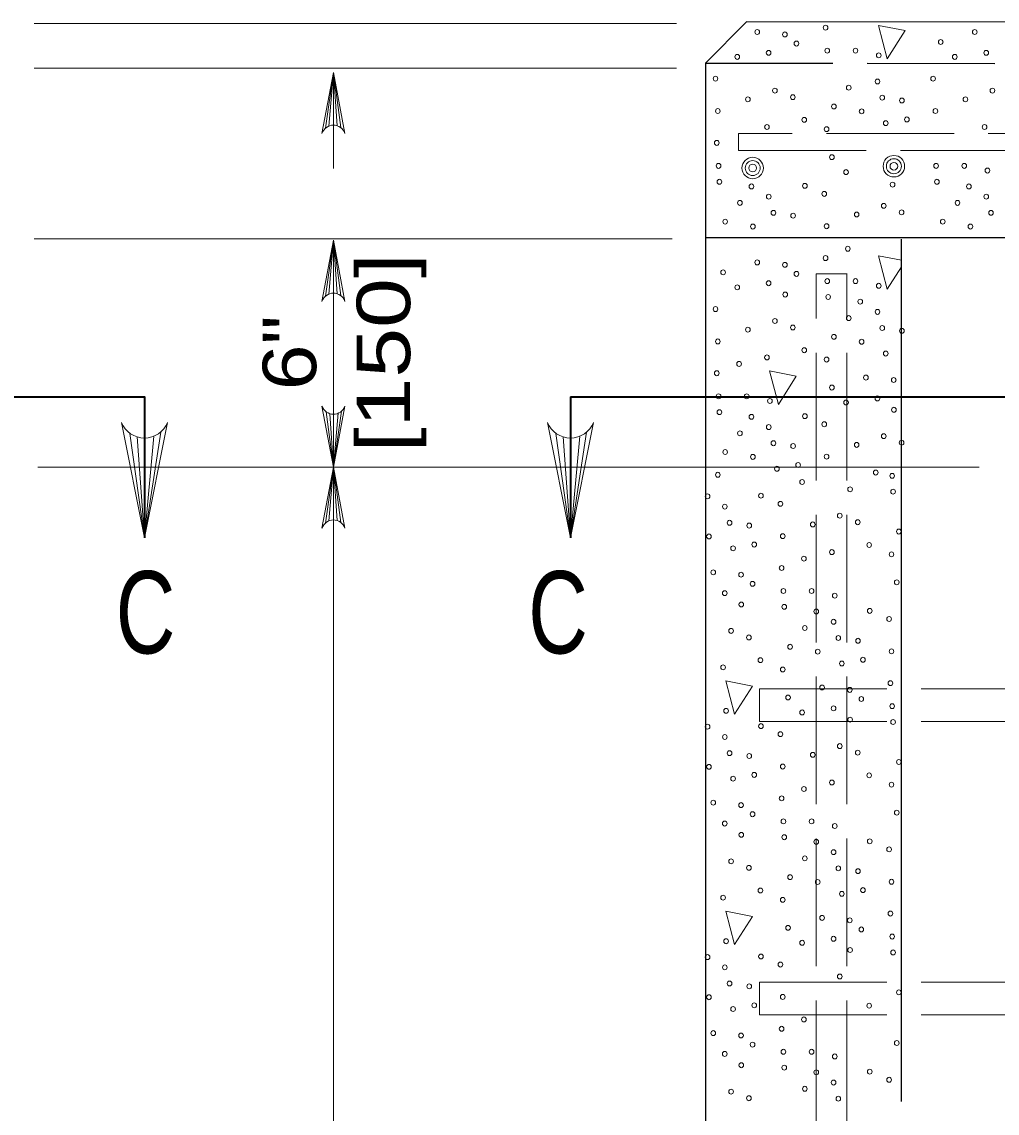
# Model space of a CAD drawing. Extents: x 1329.9 to 1363.9, y 715.5 to 737.5.
# Drawn here: x 1338.52 to 1341.364, y 730.929 to 734.111 of the extents above; entities that cross this region are included whole.
import ezdxf
from ezdxf.enums import TextEntityAlignment as Align

# ---------------------------------------------------------------- set-up
doc = ezdxf.new("R2010")
doc.units = 0
doc.header["$LTSCALE"] = 0.062
doc.linetypes.add('LONG_DASHED', pattern=[7.5, 6, -1.5])
doc.layers.add('1', color=7, linetype='Continuous', lineweight=13)

msp = doc.modelspace()

# ---------------------------------------------------------------- linework, layer by layer
at = {"layer": '1'}
for p, q in [((1338.55558, 734.106), (1340.42958, 734.106)), ((1341.018, 734.10017), (1341.04367, 734.00275)), ((1341.09592, 734.08492), (1341.018, 734.10017)), ((1341.04367, 734.00275), (1341.09592, 734.08492)), ((1338.55558, 733.97533), (1340.42958, 733.97533)), ((1339.40517, 733.80017), (1339.42875, 733.96325)), ((1339.415, 733.80633), (1339.42875, 733.96325)), ((1339.42875, 733.80917), (1339.42875, 733.96325)), ((1339.4395, 733.8075), (1339.42875, 733.96325)), ((1339.45, 733.80208), (1339.42875, 733.96325)), ((1339.42875, 733.68275), (1339.42875, 733.96325)), ((1340.61017, 733.7845), (1340.61017, 733.73575)), ((1340.61017, 733.7845), (1340.69425, 733.7845)), ((1340.61017, 733.73575), (1340.69425, 733.73575)), ((1338.55558, 733.47808), (1340.41692, 733.47808)), ((1339.40517, 733.31058), (1339.42875, 733.47375)), ((1339.415, 733.31675), (1339.42875, 733.47375)), ((1339.42875, 733.31958), (1339.42875, 733.47375)), ((1339.4395, 733.31792), (1339.42875, 733.47375)), ((1339.45, 733.3125), (1339.42875, 733.47375)), ((1341.018, 733.4285), (1341.04367, 733.33117)), ((1341.08508, 733.41542), (1341.018, 733.4285)), ((1341.04367, 733.33117), (1341.08508, 733.39633)), ((1339.40742, 732.9735), (1339.42875, 732.81225)), ((1339.41792, 732.96808), (1339.42875, 732.81225)), ((1339.45225, 732.97542), (1339.42875, 732.81225)), ((1339.44242, 732.96925), (1339.42875, 732.81225)), ((1339.42875, 732.96642), (1339.42875, 732.81225)), ((1338.83542, 732.91075), (1338.878, 732.60617)), ((1338.8565, 732.9005), (1338.878, 732.60617)), ((1338.92508, 732.91433), (1338.878, 732.60617)), ((1338.90542, 732.90267), (1338.878, 732.60617)), ((1338.878, 732.89733), (1338.878, 732.60617)), ((1340.07742, 732.91075), (1340.12008, 732.60617)), ((1340.0985, 732.9005), (1340.12008, 732.60617)), ((1340.16717, 732.91433), (1340.12008, 732.60617)), ((1340.14742, 732.90267), (1340.12008, 732.60617)), ((1340.12008, 732.89733), (1340.12008, 732.60617)), ((1338.567, 732.81183), (1340.16533, 732.81183)), ((1339.40517, 732.64917), (1339.42875, 732.81225)), ((1339.415, 732.65533), (1339.42875, 732.81225)), ((1339.42875, 732.65817), (1339.42875, 732.81225)), ((1339.4395, 732.6565), (1339.42875, 732.81225)), ((1339.45, 732.651), (1339.42875, 732.81225)), ((1340.16533, 732.81183), (1341.31183, 732.81183))]:
    msp.add_line(p, q, dxfattribs=at)
at = {"layer": '1', "lineweight": 25}
for p, q in [((1340.51358, 733.98983), (1340.51358, 732.78242)), ((1340.51358, 733.48175), (1341.09175, 733.48175)), ((1341.08508, 732.804), (1341.08508, 733.47675)), ((1341.09175, 733.48175), (1343.775, 733.48175)), ((1341.08508, 730.96275), (1341.08508, 732.804)), ((1340.51358, 732.78242), (1340.51358, 729.46942))]:
    msp.add_line(p, q, dxfattribs=at)
at = {"layer": '1', "linetype": 'LONG_DASHED', "lineweight": 25}
msp.add_line((1340.51358, 733.98983), (1343.61975, 733.988), dxfattribs=at)
at = {"layer": '1', "linetype": 'LONG_DASHED'}
for p, q in [((1344.5425, 733.7845), (1340.61017, 733.7845)), ((1340.61017, 733.73575), (1344.5425, 733.73575)), ((1340.83683, 733.37567), (1340.92658, 733.37567)), ((1340.67083, 732.1655), (1345.98667, 732.1655)), ((1340.67083, 732.1655), (1340.67083, 732.07058)), ((1340.67083, 732.07058), (1345.98667, 732.07058)), ((1340.67083, 731.31067), (1345.98667, 731.31067)), ((1340.67083, 731.31067), (1340.67083, 731.21567)), ((1340.67083, 731.21567), (1345.98667, 731.21567))]:
    msp.add_line(p, q, dxfattribs=at)
at = {"layer": '1', "lineweight": 35}
msp.add_line((1340.12008, 733.01742), (1340.12008, 732.60617), dxfattribs=at)
at = {"layer": '1', "lineweight": 25}
msp.add_lwpolyline([(1343.61975, 734.10892), (1340.63383, 734.1105), (1340.51358, 733.98983)], dxfattribs=at)
at = {"layer": '1'}
for points in [[(1339.39508, 733.78517), (1339.42875, 733.96325), (1339.46233, 733.78517)], [(1339.39508, 733.29558), (1339.42875, 733.47375), (1339.46233, 733.29558)], [(1339.42875, 732.83242), (1339.42875, 733.08692), (1339.42875, 733.47375)], [(1339.46233, 732.99033), (1339.42875, 732.81225), (1339.39508, 732.99033)], [(1338.94533, 732.94267), (1338.878, 732.60617), (1338.81075, 732.94267)], [(1340.18733, 732.94267), (1340.12008, 732.60617), (1340.05275, 732.94267)], [(1339.39508, 732.63417), (1339.42875, 732.81225), (1339.46233, 732.63417)], [(1339.42875, 725.87033), (1339.42875, 729.46942), (1339.42875, 732.83242)]]:
    msp.add_lwpolyline(points, dxfattribs=at)
at = {"layer": '1', "linetype": 'LONG_DASHED'}
for points in [[(1340.83683, 729.40367), (1340.83683, 729.46942), (1340.83683, 733.37567)], [(1340.92608, 729.41367), (1340.92608, 729.46942), (1340.92608, 733.37567)]]:
    msp.add_lwpolyline(points, dxfattribs=at)
at = {"layer": '1'}
for points in [[(1340.70075, 733.09267), (1340.72642, 732.99533), (1340.77867, 733.0775)], [(1340.57275, 732.18917), (1340.59842, 732.09183), (1340.65067, 732.174)], [(1340.57275, 731.5175), (1340.59842, 731.42017), (1340.65067, 731.50233)]]:
    msp.add_lwpolyline(points, close=True, dxfattribs=at)
at = {"layer": '1', "lineweight": 35}
for points in [[(1332.47342, 733.01742), (1338.878, 733.01742), (1338.878, 732.60617)], [(1340.12008, 733.01742), (1346.51367, 733.01742), (1346.51367, 732.60617)]]:
    msp.add_lwpolyline(points, dxfattribs=at)
at = {"layer": '1'}
for centre, radius in [((1340.65149, 733.68422), 0.03133), ((1340.65149, 733.68422), 0.0219), ((1340.65149, 733.68422), 0.01122), ((1341.06314, 733.68951), 0.03133), ((1341.06314, 733.68951), 0.0219), ((1341.06314, 733.68951), 0.01122)]:
    msp.add_circle(centre, radius, dxfattribs=at)
for centre in [(1338.87794, 732.9698), (1340.11998, 732.9698)]:
    msp.add_arc(centre, 0.07261, 202.08782, 337.91395, dxfattribs=at)
for centre in [(1340.66458, 734.08078), (1340.74541, 734.07378), (1340.86388, 734.09343), (1341.29897, 734.08078), (1340.77908, 734.0472), (1341.19964, 734.05173), (1340.60637, 734.00819), (1340.69799, 734.02), (1340.86901, 734.02632), (1340.95127, 734.02632), (1341.01889, 734.01272), (1341.24077, 734.00819), (1341.33239, 734.02), (1340.54293, 733.94472), (1341.17733, 733.94472), (1340.71628, 733.90996), (1340.9315, 733.91841), (1341.01545, 733.93654), (1341.35068, 733.90996), (1340.63746, 733.8846), (1340.76851, 733.89093), (1341.0292, 733.88942), (1341.08656, 733.88119), (1341.27185, 733.8846), (1340.5498, 733.85035), (1340.88841, 733.86373), (1340.96919, 733.84951), (1341.1842, 733.85035), (1340.80187, 733.82471), (1341.0394, 733.81503), (1341.1011, 733.82595), (1340.69312, 733.80384), (1340.867, 733.79751), (1341.32752, 733.80384), (1340.54668, 733.75761), (1340.55181, 733.6905), (1340.88244, 733.71591), (1341.18621, 733.6905), (1341.26847, 733.6905), (1340.92357, 733.67236), (1341.33609, 733.6769), (1340.55435, 733.64427), (1340.64776, 733.63067), (1340.80361, 733.63246), (1341.05941, 733.63595), (1341.18875, 733.64427), (1341.28216, 733.63067), (1340.69825, 733.60072), (1340.86013, 733.60889), (1341.33265, 733.60072), (1340.6143, 733.58259), (1341.03348, 733.57414), (1341.2487, 733.58259), (1340.57121, 733.5279), (1340.712, 733.55359), (1340.76936, 733.54537), (1340.95465, 733.54878), (1341.08571, 733.55511), (1341.20561, 733.5279), (1341.3464, 733.55359), (1340.65199, 733.51369), (1340.867, 733.51453), (1341.28639, 733.51369), (1340.92891, 733.44899), (1340.66458, 733.40913), (1340.74541, 733.40214), (1340.86388, 733.42178), (1340.56524, 733.38009), (1340.77908, 733.37555), (1340.60637, 733.33654), (1340.69799, 733.34835), (1340.86901, 733.35468), (1340.95127, 733.35468), (1341.01889, 733.34107), (1340.74625, 733.31538), (1340.87155, 733.30844), (1340.54293, 733.27307), (1340.96496, 733.29484), (1340.9315, 733.24676), (1341.01545, 733.2649), (1340.63746, 733.21296), (1340.71628, 733.23831), (1340.76851, 733.21928), (1341.0292, 733.21777), (1341.08656, 733.20954), (1340.5498, 733.1787), (1340.88841, 733.19208), (1340.96919, 733.17786), (1340.80187, 733.15307), (1340.61171, 733.11316), (1340.69312, 733.13219), (1340.867, 733.12587), (1341.0394, 733.14339), (1340.54668, 733.08596), (1340.98178, 733.07331), (1341.06261, 733.06632), (1340.55181, 733.01885), (1340.63407, 733.01885), (1340.88244, 733.04426), (1340.70169, 733.00525), (1340.92357, 733.00072), (1341.01519, 733.01253), (1340.55435, 732.97262), (1340.64776, 732.95902), (1340.80361, 732.96081), (1341.06345, 732.97956), (1340.69825, 732.92908), (1340.86013, 732.93725), (1340.6143, 732.91094), (1341.03348, 732.90249), (1340.712, 732.88195), (1340.76936, 732.87372), (1340.95465, 732.87713), (1341.08571, 732.88346), (1340.57121, 732.85626), (1340.65199, 732.84204), (1340.867, 732.84288), (1340.7222, 732.80756), (1340.7839, 732.81848), (1341.01032, 732.79637), (1340.5498, 732.79004), (1340.79556, 732.76884), (1341.05821, 732.78698), (1340.93545, 732.74768), (1341.06074, 732.74074), (1340.51976, 732.72714), (1340.67561, 732.72893), (1340.73212, 732.70537), (1340.57025, 732.6972), (1340.90547, 732.67061), (1340.58399, 732.65007), (1340.64135, 732.64184), (1340.82665, 732.64526), (1340.95771, 732.65158), (1340.52399, 732.61017), (1340.739, 732.61101), (1341.07761, 732.62438), (1340.5942, 732.57569), (1340.65589, 732.5866), (1340.99107, 732.58537), (1340.8009, 732.54546), (1340.88232, 732.56449), (1341.0562, 732.55817), (1340.73588, 732.51826), (1340.53657, 732.50561), (1340.6174, 732.49862), (1341.07163, 732.47656), (1340.56998, 732.44483), (1340.65108, 732.47203), (1340.74101, 732.45115), (1340.82327, 732.45115), (1340.89088, 732.43755), (1340.61825, 732.41186), (1340.74354, 732.40492), (1340.83696, 732.39132), (1340.99281, 732.39311), (1340.88745, 732.36138), (1341.04932, 732.36955), (1340.58828, 732.33479), (1340.80349, 732.34324), (1340.64051, 732.31576), (1340.76041, 732.28856), (1340.90119, 732.31425), (1340.95855, 732.30602), (1340.84119, 732.27434), (1341.0562, 732.27518), (1340.56512, 732.22867), (1340.67387, 732.24955), (1340.739, 732.22235), (1340.9114, 732.23986), (1340.97309, 732.25078), (1340.85377, 732.16979), (1340.9346, 732.16279), (1341.05308, 732.18244), (1340.75443, 732.14074), (1340.96828, 732.13621), (1340.57368, 732.10173), (1340.79556, 732.0972), (1340.88718, 732.10901), (1341.05821, 732.11533), (1340.93545, 732.07604), (1341.06074, 732.0691), (1340.51976, 732.0555), (1340.67561, 732.05729), (1340.73212, 732.03373), (1340.57025, 732.02555), (1340.90547, 731.99897), (1340.58399, 731.97843), (1340.64135, 731.9702), (1340.82665, 731.97361), (1340.95771, 731.97994), (1340.52399, 731.93852), (1340.739, 731.93936), (1341.07761, 731.95274), (1340.5942, 731.90404), (1340.65589, 731.91496), (1340.99107, 731.91372), (1340.8009, 731.87382), (1340.88232, 731.89285), (1341.0562, 731.88652), (1340.73588, 731.84662), (1340.53657, 731.83397), (1340.6174, 731.82697), (1340.65108, 731.80038), (1340.74101, 731.77951), (1340.82327, 731.77951), (1341.07163, 731.80492), (1340.56998, 731.77318), (1340.89088, 731.76591), (1340.61825, 731.74022), (1340.74354, 731.73328), (1340.83696, 731.71968), (1340.99281, 731.72147), (1340.88745, 731.68973), (1341.04932, 731.6979), (1340.58828, 731.66315), (1340.80349, 731.6716), (1340.64051, 731.64412), (1340.76041, 731.61691), (1340.90119, 731.6426), (1340.95855, 731.63438), (1340.84119, 731.6027), (1341.0562, 731.60354), (1340.56512, 731.55703), (1340.67387, 731.5779), (1340.9114, 731.56822), (1340.97309, 731.57913), (1340.739, 731.5507), (1340.85377, 731.49814), (1340.9346, 731.49115), (1341.05308, 731.51079), (1340.75443, 731.4691), (1340.96828, 731.46456), (1340.57368, 731.43008), (1340.88718, 731.43736), (1341.05821, 731.44368), (1340.79556, 731.42555), (1340.93545, 731.40439), (1341.06074, 731.39745), (1340.51976, 731.38385), (1340.67561, 731.38564), (1340.57025, 731.35391), (1340.73212, 731.36208), (1340.58399, 731.30678), (1340.64135, 731.29855), (1340.90547, 731.32732), (1340.52399, 731.26687), (1340.739, 731.26771), (1341.07761, 731.28109), (1340.65589, 731.24331), (1340.99107, 731.24208), (1340.5942, 731.2324), (1340.73588, 731.17497), (1340.8009, 731.20217), (1340.53657, 731.16232), (1340.6174, 731.15533), (1340.65108, 731.12874), (1340.74101, 731.10786), (1340.82327, 731.10786), (1341.07163, 731.13327), (1340.56998, 731.10154), (1340.89088, 731.09426), (1340.61825, 731.06857), (1340.74354, 731.06163), (1340.83696, 731.04803), (1340.99281, 731.04982), (1340.88745, 731.01809), (1341.04932, 731.02626), (1340.58828, 730.9915), (1340.80349, 730.99995), (1340.64051, 730.97247), (1340.90119, 730.97096)]:
    msp.add_ellipse(centre, major_axis=(0, 0.00718), ratio=0.944544, dxfattribs=at)
for centre, major_axis in [((1339.42872, 733.77074), (0, 0.03844)), ((1339.42872, 733.28117), (0, 0.03844)), ((1339.42872, 733.00482), (0, -0.03844)), ((1339.42872, 732.61972), (0, 0.03844))]:
    msp.add_ellipse(centre, major_axis=major_axis, ratio=0.944544, start_param=5.0978942, end_param=7.4685073, dxfattribs=at)

# ---------------------------------------------------------------- texts
for s, width, p in [('[150]', 1.25, (1339.6525, 733.14567)), ('6"', 1.15, (1339.37842, 733.14567))]:
    msp.add_text(s, height=0.156, rotation=90, dxfattribs=dict(at, width=width)).set_placement(p, align=Align.CENTER)
at = {"layer": '1', "width": 0.75}
for p in [(1338.88083, 732.26925), (1340.08383, 732.26925)]:
    msp.add_text('C', height=0.24, dxfattribs=at).set_placement(p, align=Align.CENTER)

doc.saveas('drawing.dxf')
